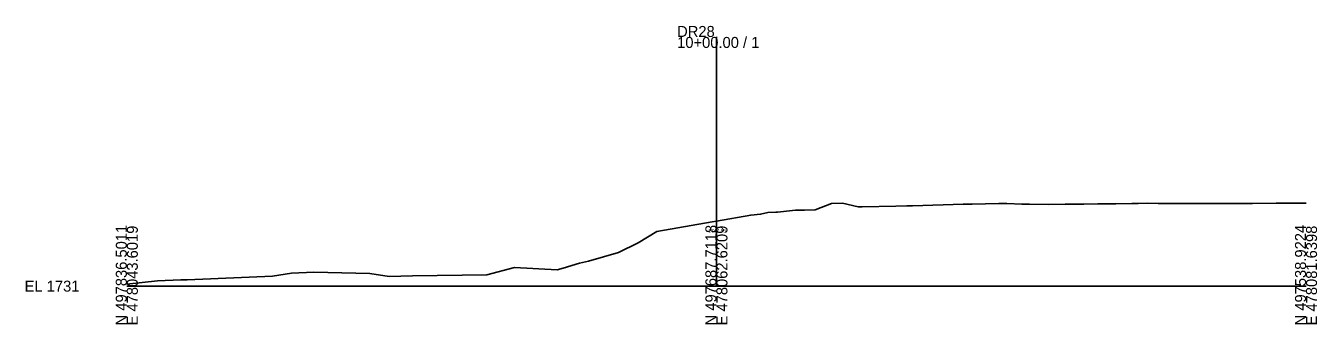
# Model space of a CAD drawing. Extents: x -26 to 303, y -10 to 3689.
# Drawn here: x -25.7 to 302.8, y -9.7 to 66.3 of the extents above; entities that cross this region are included whole.
import ezdxf

# ---------------------------------------------------------------- set-up
doc = ezdxf.new("R2010")
doc.units = 0
for name, color, linetype in [('Exist Cross Section Cell', 7, 'Continuous'), ('Exist XS Center Line Elevation Label', 7, 'Continuous'), ('Exist XS Ground Line', 7, 'Continuous')]:
    doc.layers.add(name, color=color, linetype=linetype)

msp = doc.modelspace()

# ---------------------------------------------------------------- linework, layer by layer
at = {"layer": 'Exist Cross Section Cell'}
for p, q in [((150, 0), (150, 63.47)), ((0, 0), (150, 0)), ((150, 0), (300, 0))]:
    msp.add_line(p, q, dxfattribs=at)
at = {"layer": 'Exist XS Ground Line'}
msp.add_lwpolyline([(0, 0.5), (7.82, 1.34), (13.76, 1.57), (15.38, 1.62), (37.03, 2.58), (41.87, 3.31), (47.62, 3.6), (61.82, 3.21), (66.77, 2.48), (72.69, 2.66), (91.63, 2.92), (98.66, 4.78), (109.48, 4.13), (111.01, 4.58), (115.21, 5.86), (117.45, 6.32), (125.13, 8.59), (130.09, 11.07), (134.85, 13.9), (148.89, 16.35), (150, 16.55), (158.72, 18.09), (161.23, 18.32), (163.09, 18.73), (165.13, 18.82), (165.52, 18.86), (170.09, 19.34), (172.4, 19.35), (175.14, 19.45), (179.29, 21.04), (182.04, 21.16), (186.08, 20.17), (187.07, 20.21), (195.66, 20.39), (198.43, 20.45), (199.87, 20.44), (207.68, 20.74), (212.75, 20.89), (215.09, 20.9), (221.86, 21.02), (223.91, 21.02), (227.74, 20.86), (229.66, 20.84), (234.6, 20.8), (238.69, 20.87), (239.54, 20.88), (243.48, 20.91), (247.05, 20.98), (251.64, 21), (255.66, 21.08), (256.44, 21.08), (257.26, 21.08), (259.66, 21.1), (262.35, 21.02), (270.27, 21.08), (280.16, 21.04), (281.11, 21.05), (286.38, 21.07), (292.39, 21.12), (300, 21.13)], dxfattribs=at)

# ---------------------------------------------------------------- texts
at = {"layer": 'Exist Cross Section Cell'}
for s, p in [('DR28', (140, 63.47)), ('10+00.00 / 1', (140, 60.67)), ('EL 1731', (-26, -1.4))]:
    msp.add_text(s, height=2.8, dxfattribs=at).set_placement(p)
for s, p in [('N 497836.5011', (0, -10)), ('E 478043.6019', (2.8, -10)), ('N 497687.7118', (150, -10)), ('E 478062.6209', (152.8, -10)), ('N 497538.9224', (300, -10)), ('E 478081.6398', (302.8, -10))]:
    msp.add_text(s, height=2.8, rotation=90, dxfattribs=at).set_placement(p)
at = {"layer": 'Exist XS Center Line Elevation Label'}
msp.add_text('1747.55', height=0.9, dxfattribs=at).set_placement((147.94, 13.65))

doc.saveas('drawing.dxf')
